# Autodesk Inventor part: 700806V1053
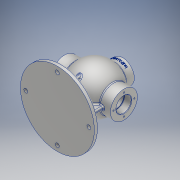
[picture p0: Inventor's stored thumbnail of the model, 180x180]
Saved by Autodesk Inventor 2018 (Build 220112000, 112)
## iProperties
Created: 2020-08
Part Number: 700806V1053
Material: Aluminum 6061
Document SubType Name: Modeling
Designer: Administrator
Density: 2.7 g/cm^3
Appearance: Aluminum - Flat
Mass: 1752.68 g
Surface Area: 1342.42 cm^2
Volume: 649.142 cm^3
Author: Administrator
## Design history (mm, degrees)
sketch "Sketch1"
  geometry: L1 (0, -53)-(0, 53); A1 r 53 centre (0, 0) between (0, 53) and (0, -53); 1 further point
  constraints: 2 end point, 2 point on circle, 1 centre point, 1 coincident
  dimensions: "d0" = 106 diameter of A1
revolve "Revolution1" sketch "Sketch1" stored, may be unused: angle "d1" = 90 deg
sketch "Sketch2"
  geometry: C1 r 27 at (0, 0); 1 further point
  constraints: 1 centre point, 1 coincident
  dimensions: "d2" = 54 diameter of C1
extrude "Extrusion1" join sketch "Sketch2" distance "d3" = 65; taper "d4" = 0 deg
workplane "Work Plane1"
sketch "Sketch3"
  geometry: C1 r 85 at (0, 0); 1 further point
  constraints: 1 centre point, 1 coincident
  dimensions: "d6" = 170 diameter of C1
extrude "Extrusion2" join sketch "Sketch3" distance "d7" = 10; taper "d8" = 0 deg
sketch "Sketch4"
  geometry: C1 r 31 at (0, 0); 1 further point
  constraints: 1 centre point, 1 coincident
  dimensions: "d9" = 62 diameter of C1
extrude "Extrusion3" join sketch "Sketch4" stored distance "d10" = 136; taper "d11" = 0 deg
sketch "Sketch5"
  geometry: L1 (4, 85)-(4, 84.906); L2 (-4, 85)-(-4, 84.906); L3 (-85, 4)-(-84.906, 4); L4 (-85, -4)-(-84.906, -4); L5 (84.906, 4)-(85, 4); L6 (84.906, -4)-(85, -4); L7 (4, -84.906)-(4, -85); L8 (-4, -84.906)-(-4, -85); L9 (52, -67.238)-(52, -85); L10 (73.321, -43)-(85, -43); L11 (-52, -67.238)-(-52, -85); L12 (-85, -43)-(-73.321, -43); L13 (-4, -43)-(4, -43); L14 (52, 85)-(52, 67.238); L15 (52, 4)-(52, -4); L16 (73.321, 43)-(85, 43); L17 (-85, 43)-(-73.321, 43); L18 (-4, 43)-(4, 43); L19 (-52, 85)-(-52, 67.238); L20 (-52, 4)-(-52, -4); L21 (4, 43)-(4, 4); L22 (4, -4)-(4, -43); L23 (-4, 43)-(-4, 4); L24 (-4, -4)-(-4, -43); L25 (-52, 4)-(-4, 4); L26 (4, 4)-(52, 4); L27 (-52, -4)-(-4, -4); L28 (4, -4)-(52, -4); 1 further point
  constraints: 56 end point, 17 other
extrude "Extrusion4" join sketch "Sketch5" stored distance "d20" = 136; taper "d21" = 0 deg
fillet "Fillet1" dims "d22" = 3
fillet "Fillet2" dims "d23" = 3
sketch "Sketch6"
  geometry: C1 r 17.5 at (0, 0); 1 further point
  constraints: 1 centre point, 1 coincident
  dimensions: "d24" = 35 diameter of C1
extrude "Extrusion5" cut sketch "Sketch6" distance "d25" = 16; taper "d26" = 0 deg
sketch "Sketch9"
  geometry: L1 (0, -43)-(0, 43); L2 (-4, 40)-(-4, 7) reference; A1 r 43 centre (0, 0) between (0, 43) and (0, -43); 4 further points; 1 other entity
  constraints: 2 end point, 2 point on circle, 1 centre point, 1 coincident, 1 parallel, 1 other
revolve "Revolution2" sketch "Sketch9" stored, may be unused: angle "d34" = 90 deg
sketch "Sketch10"
  geometry: C1 r 13 at (0, 0); 1 further point
  constraints: 1 centre point, 1 coincident
  dimensions: "d35" = 26 diameter of C1
extrude "Extrusion8" cut sketch "Sketch10" stored distance "d36" = 1.75; taper "d37" = 0 deg
chamfer "Chamfer1" distance "d38" = 1; stored, may be unused: second distance "d39" = 2, angle "d40" = 45 deg
fillet "Fillet3" dims "d41" = 3
sketch "Sketch11"
  geometry: A1 r 72.5 centre (0, 0) between (0, 72.5) and (72.5, 0); 3 further points
  constraints: 4 point on circle, 1 centre point, 1 coincident
  dimensions: "d43" = 145 diameter of A1
hole "Hole1" sketch "Sketch11" at (0, 72.5), (72.5, 0), (-72.5, 0), (0, -72.5) diameter "d44" = 9; stored, may be unused: countersink angle "d48" = 90 deg, drill point angle "d50" = 118 deg; dims "d45" = 6, "d46" = 4, "d47" = 2, "d49" = 8
sketch "Sketch12"
  geometry: A1 r 24 centre (0, 0) between (0, 24) and (-24, 0); 3 further points
  constraints: 4 point on circle, 1 centre point, 1 coincident
  dimensions: "d51" = 48 diameter of A1
hole "Hole2" sketch "Sketch12" at (0, 24), (-24, 0), (24, 0), (0, -24) diameter "d52" = 3.242; stored, may be unused: countersink angle "d56" = 90 deg, drill point angle "d58" = 118 deg; dims "d53" = 12, "d54" = 4, "d55" = 2, "d57" = 15
mirror "Mirror1"
sketch "Sketch13"
  geometry: A1 r 20 centre (0, 0) between (-20, 0) and (0, 20); 3 further points
  constraints: 4 point on circle, 1 centre point, 1 coincident
  dimensions: "d59" = 40 diameter of A1
hole "Hole3" sketch "Sketch13" at (-20, 0), (0, 20), (20, 0), (0, -20) diameter "d60" = 3.242; stored, may be unused: countersink angle "d64" = 90 deg, drill point angle "d66" = 118 deg; dims "d61" = 12, "d62" = 4, "d63" = 2, "d65" = 15
workplane "Work Plane2"
sketch "Sketch14"
  geometry: L1 (0, 47.286)-(0, 65); L2 (27, 47.286)-(27, 65) reference; L3 (-27.233, 56)-(27, 56); L4 (-20.856, 59.002)-(20.623, 59.002); L5 (20.623, 59.002)-(20.623, 52.998); L6 (20.623, 52.998)-(-20.856, 52.998); L7 (-20.856, 52.998)-(-20.856, 59.002); L8 (-93.742, 96.348)-(-52.263, 96.348); 3 further points
  constraints: 6 end point, 2 midpoint, 2 other
emboss "Emboss1" sketch "Sketch14" dims "d69" = 0.5, "d70" = 0
sketch "Sketch15"
  geometry: C1 r 17.5 at (0, 0); 1 further point
  constraints: 1 centre point, 1 coincident
  dimensions: "d71" = 35 diameter of C1
extrude "Extrusion9" cut sketch "Sketch15" distance "d72" = 16; taper "d73" = 0 deg
sketch "Sketch16"
  geometry: C1 r 18.5 at (0, 0); 1 further point
  constraints: 1 centre point, 1 coincident
  dimensions: "d74" = 37 diameter of C1
extrude "Extrusion10" cut sketch "Sketch16" distance "d75" = 1.75; taper "d76" = 0 deg
sketch "Sketch17"
  geometry: C1 r 17.5 at (0, 0); 1 further point
  constraints: 1 centre point, 1 coincident
  dimensions: "d77" = 35 diameter of C1
extrude "Extrusion11" cut sketch "Sketch17" extent not by distance; stored distance "d78" = 1.75; taper "d79" = 0 deg
chamfer "Chamfer2" distance "d80" = 1; stored, may be unused: second distance "d81" = 2, angle "d82" = 45 deg
body "Solid1"
other parameters: "d5" = -85, "d12" = 4, "d13" = 4, "d14" = 4, "d15" = 4, "d16" = 52, "d17" = 52, "d18" = 43, "d19" = 43
